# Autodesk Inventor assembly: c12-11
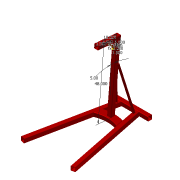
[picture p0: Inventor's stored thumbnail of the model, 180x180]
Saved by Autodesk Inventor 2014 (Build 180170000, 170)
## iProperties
Created: 2011-01
Part Number: c12-11
Document SubType Name: Assembly
Designer: Thom Tremblay
_SolveAssemblyDoc: Frame Generator Solve Assembly
_Version: 15.0.0
Author: Thom Tremblay
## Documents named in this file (3)
- C:\Inventor 2014 Essentials\Assemblies\Chapter 12\c12-11.iam
- C:\Inventor 2014 Essentials\Assemblies\Chapter 12\Frame\Frame c12-11.iam
- C:\Inventor 2014 Essentials\Parts\Chapter 12\c12-03.ipt
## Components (2 placed, 2 different names)
1. c12-03:1
2. Frame c12-11:1 [sub-assembly]
